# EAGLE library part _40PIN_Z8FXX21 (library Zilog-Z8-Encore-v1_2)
Z8 Encore, DIP-40 Package
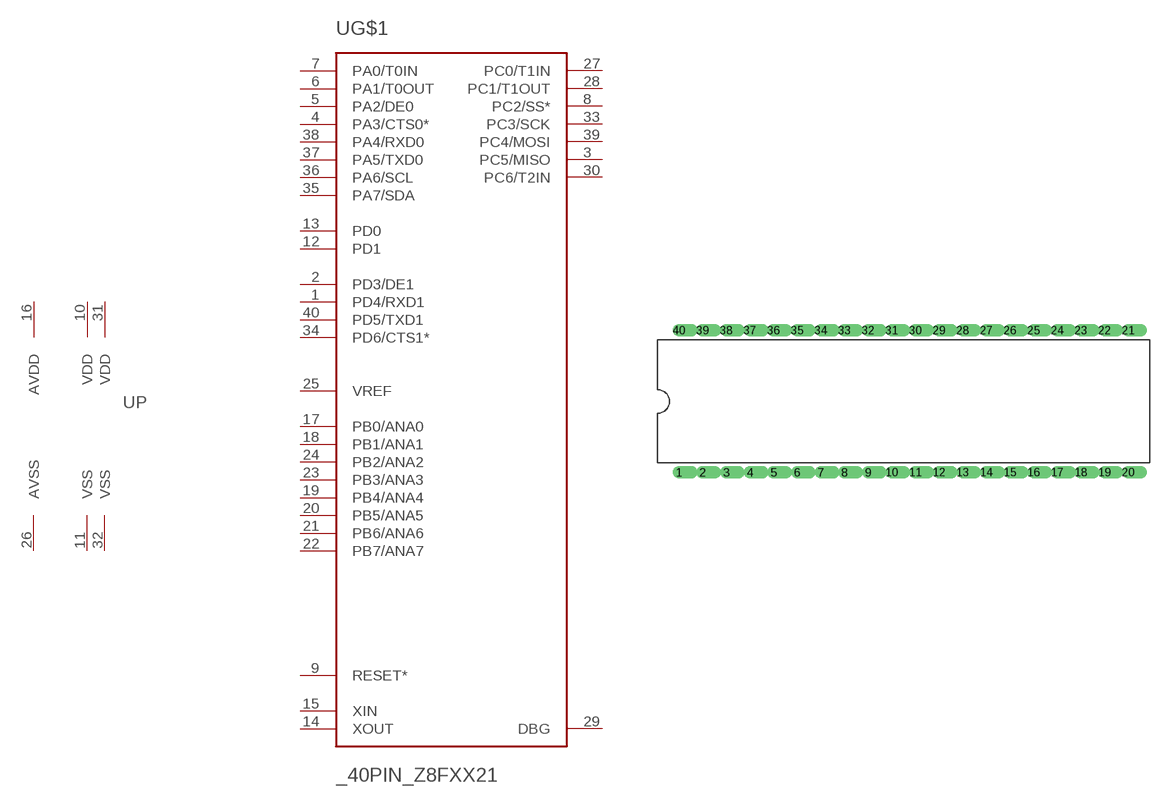
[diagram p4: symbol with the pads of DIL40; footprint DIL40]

Designator prefix U; gates G$1=Z8FXX21-DIP P=PWR_40-PIN

## _40PIN_Z8FXX21PM  [DIL40]
1  G$1:PD4/RXD1
2  G$1:PD3/DE1
3  G$1:PC5/MISO
4  G$1:PA3/CTS0*
5  G$1:PA2/DE0
6  G$1:PA1/T0OUT
7  G$1:PA0/T0IN
8  G$1:PC2/SS*
9  G$1:RESET*  in
10  P:VDD  pwr
11  P:VSS  pwr
12  G$1:PD1
13  G$1:PD0
14  G$1:XOUT  out
15  G$1:XIN  in
16  P:AVDD  pwr
17  G$1:PB0/ANA0
18  G$1:PB1/ANA1
19  G$1:PB4/ANA4
20  G$1:PB5/ANA5
21  G$1:PB6/ANA6
22  G$1:PB7/ANA7
23  G$1:PB3/ANA3
24  G$1:PB2/ANA2
25  G$1:VREF  pas
26  P:AVSS  pwr
27  G$1:PC0/T1IN
28  G$1:PC1/T1OUT
29  G$1:DBG
30  G$1:PC6/T2IN
31  P:VDD  pwr
32  P:VSS  pwr
33  G$1:PC3/SCK
34  G$1:PD6/CTS1*
35  G$1:PA7/SDA
36  G$1:PA6/SCL
37  G$1:PA5/TXD0
38  G$1:PA4/RXD0
39  G$1:PC4/MOSI
40  G$1:PD5/TXD1

## Footprint DIL40 (pad centres in mm)
Dual In-Line Package (DIP)
drill 0.813 offset: 1 -24.13,-7.62; 2 -21.59,-7.62; 3 -19.05,-7.62; 4 -16.51,-7.62; 5 -13.97,-7.62; 6 -11.43,-7.62; 7 -8.89,-7.62; 8 -6.35,-7.62; 9 -3.81,-7.62; 10 -1.27,-7.62; 11 1.27,-7.62; 12 3.81,-7.62; 13 6.35,-7.62; 14 8.89,-7.62; 15 11.43,-7.62; 16 13.97,-7.62; 17 16.51,-7.62; 18 19.05,-7.62; 19 21.59,-7.62; 20 24.13,-7.62; 21 24.13,7.62; 22 21.59,7.62; 23 19.05,7.62; 24 16.51,7.62; 25 13.97,7.62; 26 11.43,7.62; 27 8.89,7.62; 28 6.35,7.62; 29 3.81,7.62; 30 1.27,7.62; 31 -1.27,7.62; 32 -3.81,7.62; 33 -6.35,7.62; 34 -8.89,7.62; 35 -11.43,7.62; 36 -13.97,7.62; 37 -16.51,7.62; 38 -19.05,7.62; 39 -21.59,7.62; 40 -24.13,7.62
